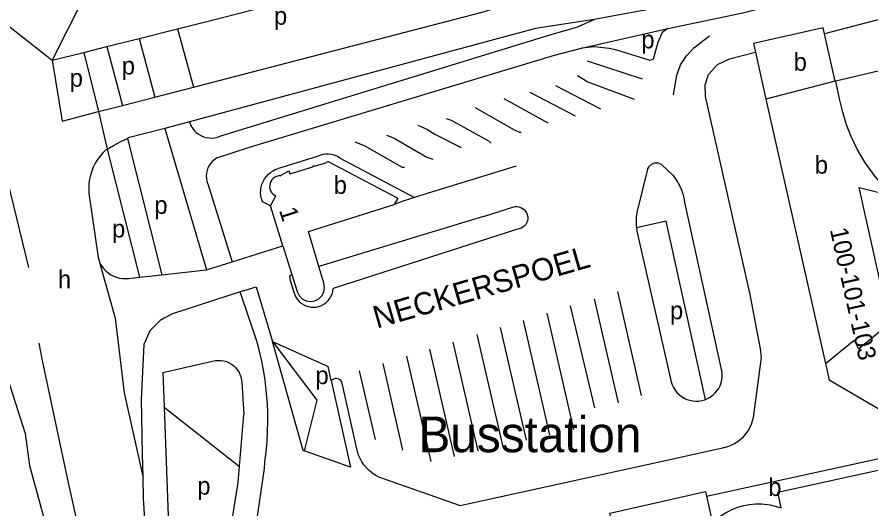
# Model space of a CAD drawing. Extents: x 160673 to 161924, y 382258 to 384145.
# Drawn here: x 161236.5 to 161427.8, y 383827.1 to 383937.4 of the extents above; entities that cross this region are included whole.
import ezdxf

# ---------------------------------------------------------------- set-up
doc = ezdxf.new("R2010")
doc.units = 0
for name, color, linetype in [('BLT_Basislijn', 7, 'Continuous'), ('BLT_Bebouwing', 7, 'Continuous'), ('BLT_Bebouwing_beschrifting', 7, 'Continuous'), ('BLT_Centroide', 7, 'Continuous'), ('BLT_Huisnummer_reeks', 7, 'Continuous'), ('BLT_Onderdoorgang_en_onderverdeling', 7, 'Continuous'), ('BLT_Straatnaam', 7, 'Continuous'), ('BLT_Vlakafsluiter', 7, 'Continuous')]:
    doc.layers.add(name, color=color, linetype=linetype)

msp = doc.modelspace()

# ---------------------------------------------------------------- linework, layer by layer
at = {"layer": 'BLT_Basislijn'}
for p, q in [((161381.23, 383939.7), (161365.8, 383936.85)), ((161436.91, 383938.75), (161417.39, 383933.66)), ((161362.92, 383930.38), (161382.26, 383934.81)), ((161263.81, 383932.59), (161272.46, 383934.77)), ((161272.46, 383934.77), (161275.99, 383921.7)), ((161256.6, 383930.77), (161263.81, 383932.59)), ((161263.81, 383932.59), (161267.35, 383919.45)), ((161244.38, 383927.69), (161251.46, 383929.47)), ((161251.46, 383929.47), (161256.6, 383930.77)), ((161251.46, 383929.47), (161254.75, 383916.18)), ((161256.6, 383930.77), (161260.1, 383917.57)), ((161364.23, 383927.55), (161376.52, 383923.57)), ((161439.38, 383927.65), (161419.89, 383923.01)), ((161267.35, 383919.45), (161275.99, 383921.7)), ((161357.11, 383922.03), (161367.2, 383916.84)), ((161351.36, 383920.57), (161361.53, 383915.25)), ((161254.75, 383916.18), (161260.1, 383917.57)), ((161260.1, 383917.57), (161267.35, 383919.45)), ((161345.5, 383919.11), (161355.41, 383913.66)), ((161275.08, 383913.86), (161269.62, 383912.42)), ((161269.62, 383912.42), (161261.4, 383910.27)), ((161269.62, 383912.42), (161278.94, 383880.73)), ((161261.21, 383910.18), (161261.4, 383910.27)), ((161261.21, 383910.18), (161268.91, 383879.6)), ((161281.27, 383905.81), (161288.54, 383908.19)), ((161256.38, 383907.59), (161256.67, 383907.76)), ((161256.67, 383907.76), (161263.89, 383879.05)), ((161303.74, 383906.15), (161294.83, 383903.38)), ((161308.73, 383905.85), (161325.52, 383896.89)), ((161383.45, 383901.83), (161380.86, 383904.29)), ((161233.67, 383903.35), (161239.02, 383881.24)), ((161348.33, 383903.93), (161327.4, 383897.49)), ((161377.71, 383903.27), (161375.31, 383893.54)), ((161279.26, 383899.78), (161284.66, 383882.51)), ((161252.59, 383897.88), (161254.68, 383883.45)), ((161325.52, 383896.89), (161322.33, 383895.86)), ((161327.4, 383897.49), (161325.52, 383896.89)), ((161293.24, 383895.04), (161291.43, 383895.97)), ((161322.33, 383895.86), (161321, 383895.35)), ((161341.01, 383892.65), (161348.01, 383894.88)), ((161394.24, 383858.71), (161385.99, 383896.19)), ((161348.59, 383889.79), (161307.32, 383876.51)), ((161375.34, 383889.39), (161382.9, 383856.24)), ((161254.68, 383883.45), (161254.86, 383882.77)), ((161254.86, 383882.77), (161255.05, 383882.11)), ((161278.94, 383880.73), (161284.66, 383882.51)), ((161263.89, 383879.05), (161268.91, 383879.6)), ((161261.52, 383878.79), (161263.89, 383879.05)), ((161287.1, 383875.99), (161286.45, 383875.78)), ((161290.28, 383864.49), (161286.45, 383875.78)), ((161307.31, 383876.41), (161307.32, 383876.51)), ((161370.97, 383875.83), (161376.32, 383852.54)), ((161365.77, 383874.23), (161371.14, 383850.89)), ((161360.43, 383872.59), (161365.82, 383849.74)), ((161258.44, 383869.86), (161260.45, 383853.11)), ((161355.14, 383870.97), (161361.13, 383844.91)), ((161349.9, 383869.35), (161355.8, 383843.7)), ((161339.51, 383866.16), (161345.22, 383841.31)), ((161344.71, 383867.76), (161350.51, 383842.51)), ((161334.11, 383864.5), (161339.72, 383840.07)), ((161328.87, 383862.89), (161334.39, 383838.86)), ((161269.16, 383857.67), (161280.29, 383860.18)), ((161323.74, 383861.3), (161329.16, 383837.68)), ((161306.88, 383855.89), (161306.15, 383859.02)), ((161318.39, 383859.66), (161322.84, 383840.26)), ((161417.57, 383859.68), (161418.4, 383855.97)), ((161313.15, 383858.05), (161316.68, 383842.66)), ((161286.81, 383855.42), (161287.3, 383848.28)), ((161312.76, 383839.9), (161309.26, 383855.61)), ((161269.44, 383849.92), (161286.34, 383836.57)), ((161286.34, 383836.57), (161287.3, 383848.28)), ((161380.68, 383837.71), (161394.9, 383840.83)), ((161335.73, 383827.87), (161380.68, 383837.71)), ((161286.05, 383832.99), (161286.34, 383836.57)), ((161317.42, 383834.27), (161335.73, 383827.87))]:
    msp.add_line(p, q, dxfattribs=at)
for points in [[(161272.46, 383934.77), (161279.92, 383936.65), (161372.44, 383960.49), (161419.05, 383972.43)], [(161275.99, 383921.7), (161340.35, 383938.41), (161354.66, 383942.76), (161376.96, 383950.25), (161394.06, 383955.66), (161417.32, 383962.02), (161429.19, 383965.16)], [(161382.26, 383934.81), (161398.74, 383938.26), (161465.43, 383954.94)], [(161365.8, 383936.85), (161352.63, 383934.84), (161275.08, 383913.86)], [(161282.1, 383910.72), (161356.38, 383933.59), (161361.9, 383935.14), (161365.8, 383936.85)], [(161382.26, 383934.81), (161380.99, 383933.9), (161380.04, 383931.72), (161378.97, 383927.97), (161378.32, 383927.65), (161370.83, 383929.97), (161369.17, 383930.37), (161365.86, 383930.75), (161362.92, 383930.38)], [(161383.58, 383919.97), (161384.26, 383924.38), (161385.13, 383926.65), (161386.44, 383928.7), (161388.08, 383930.49), (161391.59, 383933.2)], [(161288.54, 383908.19), (161356.89, 383928.81), (161362.92, 383930.38)], [(161401.46, 383847.55), (161403.23, 383861.01), (161403.06, 383863.01), (161400.69, 383875.18), (161390.71, 383919.6), (161390.68, 383922.18), (161391.41, 383924.5), (161393.4, 383926.72), (161396.1, 383928.01), (161401.9, 383929.54)], [(161244.38, 383927.69), (161246.62, 383914.07), (161254.75, 383916.18)], [(161362.04, 383924.3), (161364.38, 383922.85), (161374.75, 383918.96)], [(161339.15, 383917.1), (161347.82, 383912.09), (161349.03, 383911.55), (161349.45, 383911.58)], [(161275.08, 383913.86), (161275.44, 383913.04), (161275.77, 383912.49), (161276.16, 383911.98), (161276.61, 383911.53), (161277.12, 383911.14), (161277.67, 383910.82), (161278.25, 383910.56), (161278.86, 383910.38), (161279.49, 383910.28), (161280.13, 383910.26), (161280.77, 383910.32), (161281.39, 383910.46), (161281.99, 383910.67), (161282.1, 383910.72)], [(161332.62, 383914.66), (161333.74, 383914.29), (161342.12, 383909.63), (161342.66, 383909.12)], [(161326.25, 383913.11), (161328.29, 383912.27), (161330.08, 383911.12), (161336, 383908.13)], [(161256.67, 383907.76), (161258.05, 383908.57), (161259.76, 383909.48), (161261.21, 383910.18)], [(161319.24, 383910.92), (161320.98, 383910.25), (161328.27, 383905.99), (161329.66, 383905.53)], [(161312.17, 383909.44), (161314.26, 383908.61), (161322.77, 383903.74), (161323.25, 383903.74)], [(161256.38, 383907.59), (161255.69, 383906.93), (161255.06, 383906.2), (161254.49, 383905.43), (161253.99, 383904.61), (161253.56, 383903.76), (161253.2, 383902.86), (161252.92, 383901.95), (161252.71, 383901.01), (161252.58, 383900.06), (161252.53, 383899.1), (161252.57, 383898.14), (161252.59, 383897.88)], [(161308.73, 383905.85), (161308.15, 383906.16), (161307.54, 383906.39), (161306.9, 383906.54), (161306.25, 383906.62), (161305.6, 383906.62), (161304.95, 383906.53), (161304.31, 383906.37), (161303.74, 383906.15)], [(161281.27, 383905.81), (161280.75, 383905.47), (161280.28, 383905.07), (161279.87, 383904.61), (161279.53, 383904.1), (161279.25, 383903.55), (161279.04, 383902.97), (161278.91, 383902.36), (161278.86, 383901.75), (161278.89, 383901.14), (161279, 383900.53), (161279.19, 383899.94), (161279.26, 383899.78)], [(161380.86, 383904.29), (161380.5, 383904.49), (161380.11, 383904.61), (161379.7, 383904.65), (161379.29, 383904.61), (161378.9, 383904.5), (161378.54, 383904.31), (161378.22, 383904.05), (161377.95, 383903.74), (161377.76, 383903.38), (161377.71, 383903.27)], [(161291.43, 383895.97), (161291.23, 383896.61), (161291.09, 383897.27), (161291.04, 383897.94), (161291.06, 383898.61), (161291.17, 383899.27), (161291.35, 383899.92), (161291.61, 383900.53), (161291.94, 383901.12), (161292.34, 383901.66), (161292.8, 383902.15), (161293.32, 383902.58), (161293.88, 383902.94), (161294.48, 383903.24), (161294.83, 383903.38)], [(161383.45, 383901.83), (161384.03, 383901.09), (161384.55, 383900.3), (161384.99, 383899.48), (161385.36, 383898.62), (161385.66, 383897.73), (161385.88, 383896.82), (161385.99, 383896.19)], [(161348.01, 383894.88), (161348.46, 383894.9), (161348.91, 383894.84), (161349.34, 383894.69), (161349.74, 383894.48), (161350.09, 383894.2), (161350.39, 383893.86), (161350.63, 383893.47), (161350.79, 383893.05), (161350.88, 383892.61), (161350.88, 383892.15), (161350.81, 383891.71), (161350.66, 383891.28), (161350.44, 383890.89), (161350.15, 383890.54), (161349.81, 383890.25), (161349.42, 383890.02), (161348.99, 383889.86), (161348.59, 383889.79)], [(161375.31, 383893.54), (161375.19, 383892.56), (161375.15, 383891.58), (161375.18, 383890.6), (161375.24, 383890.14)], [(161341.01, 383892.65), (161322.76, 383887.12), (161304.11, 383881.47)], [(161390.69, 383851.62), (161381.87, 383891.63), (161375.24, 383890.14)], [(161375.24, 383890.14), (161375.3, 383889.63), (161375.34, 383889.39)], [(161284.66, 383882.51), (161296, 383886.05)], [(161255.05, 383882.11), (161255.49, 383881.52), (161255.9, 383880.96), (161256.37, 383880.45), (161256.9, 383879.99), (161257.47, 383879.59), (161258.09, 383879.27), (161258.74, 383879.02), (161259.42, 383878.84), (161260.11, 383878.74), (161260.8, 383878.72), (161261.52, 383878.79)], [(161268.91, 383879.6), (161278.81, 383880.69), (161278.94, 383880.73)], [(161298.06, 383879.64), (161297.95, 383879.61), (161297.51, 383879.26), (161297.64, 383878.3), (161298.52, 383875.68)], [(161286.45, 383875.78), (161271.33, 383870.84), (161269.42, 383869.89), (161268.52, 383869.33), (161266.21, 383867), (161264.86, 383863.97), (161264.3, 383851.67), (161264.48, 383839.31), (161264.62, 383834.33)], [(161287.1, 383875.99), (161290.03, 383876.89), (161293.67, 383864.66)], [(161298.52, 383875.68), (161298.7, 383875.11), (161298.96, 383874.57), (161299.29, 383874.07), (161299.68, 383873.62), (161300.13, 383873.23), (161300.63, 383872.9), (161301.17, 383872.64), (161301.74, 383872.45), (161302.33, 383872.34), (161302.92, 383872.31), (161303.52, 383872.36), (161304.1, 383872.49), (161304.66, 383872.69), (161305.19, 383872.97), (161305.68, 383873.32), (161306.12, 383873.72), (161306.5, 383874.19), (161306.81, 383874.7), (161307.05, 383875.24), (161307.22, 383875.82), (161307.31, 383876.41)], [(161255.37, 383799.71), (161247.75, 383833.99), (161242.16, 383860.4), (161241.46, 383864.27)], [(161292.02, 383837.62), (161292.3, 383839.9), (161292.5, 383842.19), (161292.62, 383844.49), (161292.67, 383846.79), (161292.63, 383849.09), (161292.51, 383851.39), (161292.32, 383853.68), (161292.04, 383855.97), (161291.68, 383858.24), (161291.25, 383860.5), (161290.74, 383862.74), (161290.28, 383864.49)], [(161293.67, 383864.66), (161303.62, 383851.45), (161300.78, 383840.1)], [(161300.78, 383840.1), (161300.56, 383840.18), (161293.67, 383864.66)], [(161293.67, 383864.66), (161306.15, 383859.02)], [(161232.13, 383863.24), (161238.32, 383843.97), (161239.28, 383836.83), (161263.75, 383747.21)], [(161280.29, 383860.18), (161280.91, 383860.33), (161281.54, 383860.39), (161282.18, 383860.38), (161282.81, 383860.29), (161283.42, 383860.12), (161284, 383859.87), (161284.55, 383859.56), (161285.06, 383859.17), (161285.51, 383858.73), (161285.9, 383858.23), (161286.23, 383857.69), (161286.49, 383857.11), (161286.67, 383856.5), (161286.78, 383855.87), (161286.81, 383855.42)], [(161390.69, 383851.62), (161391.19, 383851.83), (161391.79, 383852.16), (161392.34, 383852.56), (161392.84, 383853.02), (161393.29, 383853.54), (161393.67, 383854.11), (161393.98, 383854.71), (161394.22, 383855.35), (161394.38, 383856.01), (161394.47, 383856.69), (161394.47, 383857.37), (161394.4, 383858.05), (161394.24, 383858.71)], [(161269.16, 383857.67), (161269.44, 383849.92)], [(161306.88, 383855.89), (161311.17, 383836.46), (161300.78, 383840.1)], [(161309.26, 383855.61), (161309.03, 383855.88), (161308.75, 383856.1), (161308.42, 383856.24), (161308.07, 383856.31), (161307.72, 383856.3), (161307.37, 383856.2), (161307.06, 383856.04), (161306.88, 383855.89)], [(161382.9, 383856.24), (161383.04, 383855.57), (161383.25, 383854.92), (161383.54, 383854.3), (161383.9, 383853.72), (161384.33, 383853.19), (161384.81, 383852.71), (161385.35, 383852.29), (161385.93, 383851.93), (161386.55, 383851.65), (161387.2, 383851.44), (161387.87, 383851.31), (161388.55, 383851.25), (161389.23, 383851.28), (161389.9, 383851.39), (161390.56, 383851.57), (161390.69, 383851.62)], [(161459.57, 383837.36), (161452.77, 383835.82), (161418.4, 383855.97)], [(161269.44, 383849.92), (161270.45, 383821.38), (161270.94, 383812.22)], [(161394.9, 383840.83), (161395.7, 383841.06), (161396.48, 383841.36), (161397.23, 383841.74), (161397.93, 383842.19), (161398.59, 383842.7), (161399.2, 383843.27), (161399.75, 383843.9), (161400.24, 383844.58), (161400.66, 383845.3), (161401.01, 383846.06), (161401.28, 383846.85), (161401.46, 383847.55)], [(161317.42, 383834.27), (161316.68, 383834.68), (161315.98, 383835.16), (161315.33, 383835.7), (161314.74, 383836.3), (161314.2, 383836.95), (161313.73, 383837.65), (161313.32, 383838.39), (161312.99, 383839.17), (161312.76, 383839.9)], [(161291.77, 383814.32), (161288.79, 383815.27), (161290.41, 383825.95), (161291.95, 383836.18), (161292.02, 383837.62)], [(161264.62, 383834.33), (161264.76, 383829.35), (161265.17, 383822.72), (161266.33, 383811.03)], [(161285.59, 383830.23), (161286.05, 383832.99)], [(161283.24, 383814.81), (161284.89, 383825.98), (161285.59, 383830.23)]]:
    msp.add_lwpolyline(points, dxfattribs=at)
at = {"layer": 'BLT_Bebouwing'}
for p, q in [((161417.39, 383933.66), (161417.09, 383935)), ((161419.79, 383922.98), (161417.39, 383933.66)), ((161401.46, 383931.49), (161401.9, 383929.54)), ((161401.9, 383929.54), (161404.27, 383919)), ((161295.46, 383901.79), (161297.35, 383902.91)), ((161293.24, 383895.04), (161294.45, 383897.29)), ((161296, 383886.05), (161293.24, 383895.04))]:
    msp.add_line(p, q, dxfattribs=at)
for points in [[(161417.09, 383935), (161401.46, 383931.49)], [(161417.57, 383859.68), (161424.01, 383864.92), (161425.01, 383863.01), (161430.48, 383867.49), (161429.96, 383869.77), (161431.44, 383870.97), (161425.13, 383899.18), (161430.54, 383897.81), (161432.97, 383897.24), (161430.25, 383899.84), (161428.47, 383901.94), (161426.38, 383904.87), (161424.69, 383907.8), (161423.33, 383910.61), (161422.34, 383913.2), (161421.45, 383916.05), (161420.77, 383919.05), (161419.89, 383923.01), (161419.79, 383922.98)], [(161404.27, 383919), (161417.57, 383859.68)], [(161302.77, 383903.83), (161302.91, 383904.08), (161303.14, 383903.95), (161305.9, 383904.8), (161306.06, 383905.1)], [(161306.06, 383905.1), (161321.78, 383896.79), (161321, 383895.35)], [(161297.35, 383902.91), (161297.57, 383902.21), (161302.77, 383903.83)], [(161295.46, 383901.79), (161295.02, 383901.75), (161294.61, 383901.64), (161294.21, 383901.46), (161293.86, 383901.2), (161293.57, 383900.89), (161293.33, 383900.52), (161293.17, 383900.12), (161293.08, 383899.7), (161293.07, 383899.27), (161293.14, 383898.84), (161293.29, 383898.43), (161293.51, 383898.06), (161293.8, 383897.73), (161294.14, 383897.46), (161294.45, 383897.29)], [(161304.11, 383881.47), (161301.78, 383889.33), (161321, 383895.35)], [(161296, 383886.05), (161298.06, 383879.64)], [(161298.06, 383879.64), (161299.26, 383875.82), (161299.69, 383874.92), (161300.38, 383874.2), (161301.25, 383873.75), (161302.21, 383873.57), (161303.17, 383873.72), (161304.06, 383874.17), (161304.78, 383874.86), (161305.22, 383875.71), (161305.38, 383876.69), (161305.24, 383877.68), (161304.11, 383881.47)], [(161390.94, 383829.94), (161431.64, 383838.86), (161434.88, 383836.95)], [(161380.18, 383828.59), (161390.7, 383830.97), (161390.94, 383829.94)], [(161342.32, 383816.5), (161370.04, 383822.66), (161369.27, 383826.16), (161380.18, 383828.59)]]:
    msp.add_lwpolyline(points, dxfattribs=at)
at = {"layer": 'BLT_Onderdoorgang_en_onderverdeling'}
msp.add_line((161419.79, 383922.98), (161404.27, 383919), dxfattribs=at)
msp.add_lwpolyline([(161390.94, 383829.94), (161392.29, 383823.93), (161393.29, 383824.83), (161394.37, 383825.64), (161395.51, 383826.35), (161396.72, 383826.95), (161397.98, 383827.44), (161399.28, 383827.81), (161400.6, 383828.06), (161401.95, 383828.19), (161403.29, 383828.2), (161404.64, 383828.09), (161405.23, 383828), (161407.7, 383827.35), (161406.92, 383830.86), (161434.88, 383836.95)], dxfattribs=at)
at = {"layer": 'BLT_Vlakafsluiter'}
for p, q in [((161251.54, 383941.96), (161244.38, 383927.69)), ((161233.86, 383935.94), (161244.38, 383927.69)), ((161254.75, 383916.18), (161256.67, 383907.76)), ((161255.05, 383882.11), (161258.44, 383869.86)), ((161260.45, 383853.11), (161264.62, 383834.33))]:
    msp.add_line(p, q, dxfattribs=at)

# ---------------------------------------------------------------- texts
at = {"layer": 'BLT_Bebouwing_beschrifting'}
msp.add_text('Busstation', height=8, dxfattribs=at).set_placement((161326.41, 383839.8))
at = {"layer": 'BLT_Centroide'}
for s, p in [('p', (161294.03, 383935.67)), ('p', (161376.33, 383930.37)), ('b', (161410.46, 383925.34)), ('p', (161259.94, 383924.5)), ('p', (161248.27, 383921.76)), ('b', (161415.2, 383902.26)), ('b', (161307.42, 383897.73)), ('p', (161267.23, 383893.24)), ('p', (161257.75, 383887.95)), ('h', (161245.62, 383876.57)), ('p', (161382.75, 383869.61)), ('p', (161303.33, 383855.06)), ('b', (161404.78, 383829.98)), ('p', (161276.85, 383830.27))]:
    msp.add_text(s, height=4, dxfattribs=at).set_placement(p)
at = {"layer": 'BLT_Huisnummer_reeks'}
for s, rotation, p in [('1', 287.8858, (161295.13, 383894.07)), ('100-101-103', 282.5994, (161418.56, 383889.73))]:
    msp.add_text(s, height=4, rotation=rotation, dxfattribs=at).set_placement(p)
at = {"layer": 'BLT_Straatnaam'}
msp.add_text('NECKERSPOEL', height=5, rotation=16.0974, dxfattribs=at).set_placement((161317.08, 383867.51))

doc.saveas('drawing.dxf')
